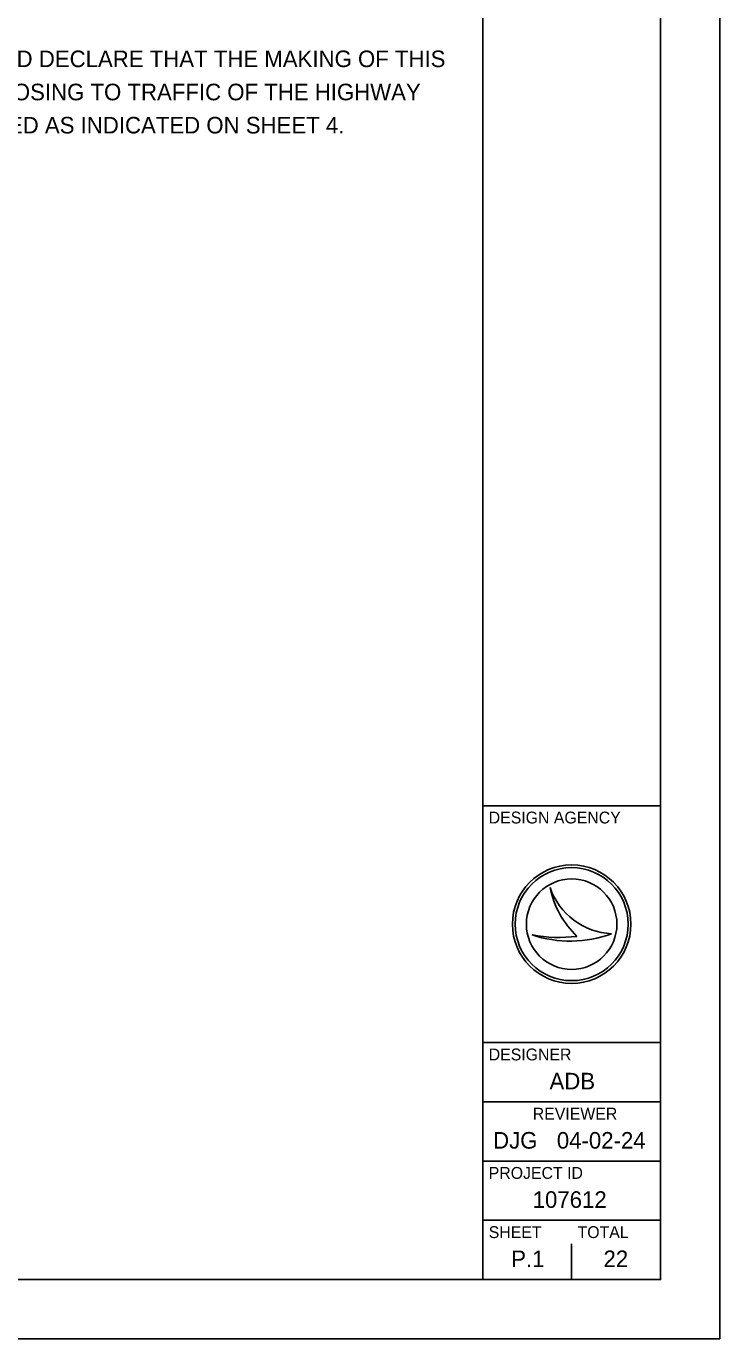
# Model space of a CAD drawing. Extents: x 0 to 34, y 0 to 22.
# Drawn here: x 28.15 to 34, y 0 to 11.08 of the extents above; entities that cross this region are included whole.
import ezdxf

# ---------------------------------------------------------------- set-up
doc = ezdxf.new("R2010")
doc.units = 0
for name, color, linetype in [('SH_Border', 7, 'Continuous'), ('SH_Cut_Line', 7, 'Continuous'), ('SH_Data', 7, 'Continuous')]:
    doc.layers.add(name, color=color, linetype=linetype)

msp = doc.modelspace()

# ---------------------------------------------------------------- linework, layer by layer
at = {"layer": 'SH_Border'}
for p, q in [((32, 0.5), (32, 21.5)), ((32, 4.5), (33.5, 4.5)), ((32, 2.5), (33.5, 2.5)), ((32, 2), (33.5, 2)), ((32, 1.5), (33.5, 1.5)), ((32, 1), (33.5, 1))]:
    msp.add_line(p, q, dxfattribs=at)
msp.add_lwpolyline([(1.5, 21.5), (33.5, 21.5), (33.5, 0.5), (1.5, 0.5)], close=True, dxfattribs=at)
at = {"layer": 'SH_Cut_Line'}
msp.add_lwpolyline([(0, 0), (34, 0), (34, 22), (0, 22)], close=True, dxfattribs=at)
at = {"layer": 'SH_Data'}
for p, q in [((32.567, 3.81), (32.567, 3.81)), ((32.75, 3.5), (32.75, 3.5)), ((32.417, 3.41), (32.417, 3.41)), ((33.087, 3.419), (33.087, 3.419)), ((32.75, 0.5), (32.75, 0.8)), ((32.375, 0.675), (32.375, 0.675))]:
    msp.add_line(p, q, dxfattribs=at)
for radius in [0.5, 0.477, 0.477, 0.382]:
    msp.add_circle((32.75, 3.5), radius, dxfattribs=at)
for centre, radius, start, end in [((33.116, 3.998), 0.58, 198.9257, 198.9319), ((33.347, 3.97), 0.796, 191.6379, 191.6421), ((33.116, 3.998), 0.58, 198.9319, 267.1657), ((33.347, 3.97), 0.796, 191.6421, 226.0947), ((32.739, 4.37), 1.013, 251.4576, 290.0832), ((32.648, 4.654), 1.266, 259.4964, 259.4995), ((32.739, 4.37), 1.013, 251.4527, 251.4576), ((32.648, 4.654), 1.266, 259.4995, 276.6672)]:
    msp.add_arc(centre, radius, start, end, dxfattribs=at)

# ---------------------------------------------------------------- texts
for s, height, p in [(' I HEREBY APPROVE THESE PLANS AND DECLARE THAT THE MAKING OF THIS', 0.14, (24.528, 10.735)), ('IMPROVEMENT WILL REQUIRE THE CLOSING TO TRAFFIC OF THE HIGHWAY', 0.14, (24.528, 10.455)), ('AND THAT DETOURS WILL BE PROVIDED AS INDICATED ON SHEET 4.', 0.14, (24.528, 10.175)), ('DESIGN AGENCY', 0.1, (32.05, 4.35)), ('DESIGNER', 0.1, (32.05, 2.35)), ('ADB', 0.14, (32.563, 2.105)), ('REVIEWER', 0.1, (32.422, 1.85)), ('DJG', 0.14, (32.087, 1.605)), ('04-02-24', 0.14, (32.625, 1.605)), ('PROJECT ID', 0.1, (32.05, 1.35)), ('107612', 0.14, (32.421, 1.105)), ('SHEET', 0.1, (32.05, 0.85)), ('TOTAL', 0.1, (32.8, 0.85)), ('P.1', 0.14, (32.24, 0.605)), ('22', 0.14, (33.019, 0.605))]:
    msp.add_text(s, height=height, dxfattribs=at).set_placement(p)

doc.saveas('drawing.dxf')
